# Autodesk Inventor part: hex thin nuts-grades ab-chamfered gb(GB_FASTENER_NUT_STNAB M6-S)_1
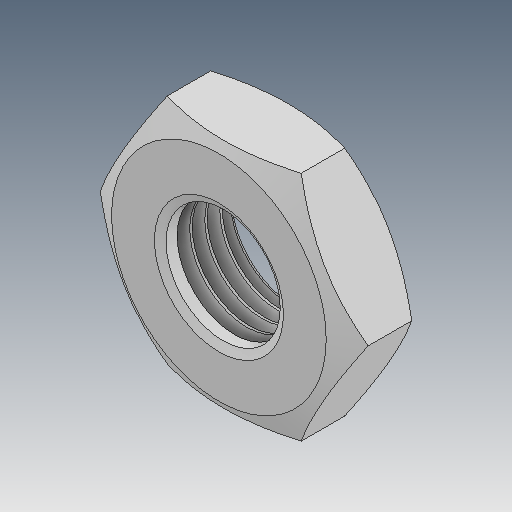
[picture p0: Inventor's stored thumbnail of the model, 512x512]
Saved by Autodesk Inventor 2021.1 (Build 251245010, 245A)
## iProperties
Created: 2019-05
Part Number: hex thin nuts-grades ab-chamfered gb(GB_FASTENER_NUT_STNAB M6-S)_1
Material: Ogólny
Document SubType Name: Modeling
Designer: user
Density: 1 g/cm^3
Appearance: Domyślna
Author: user
Revision Number: ÈÎºÎ
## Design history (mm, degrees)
feature "ÊäÈë1"
node "Bryła1"
